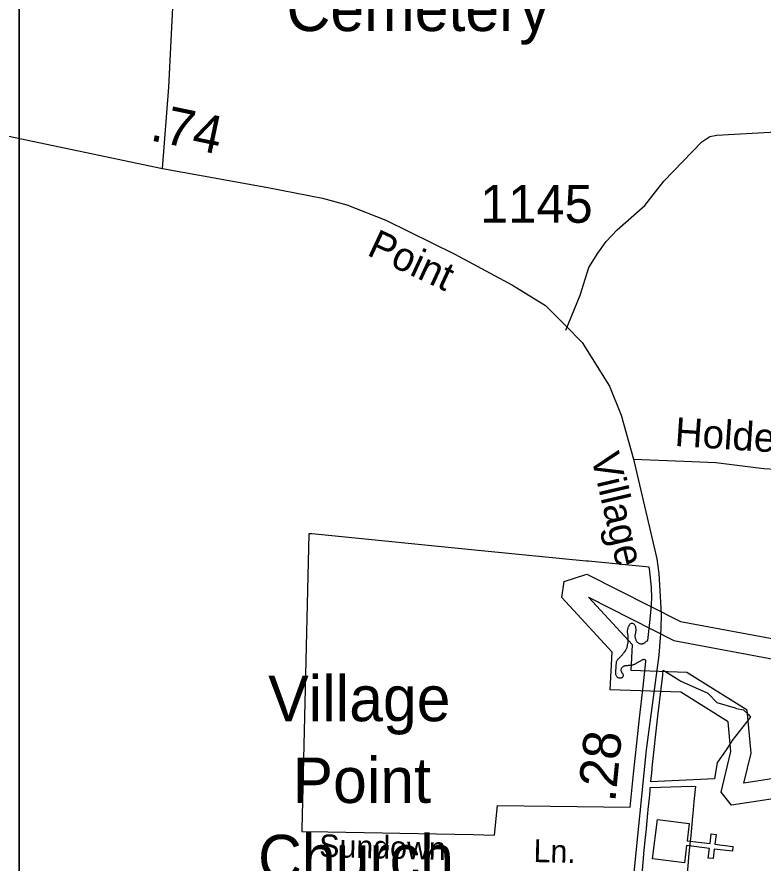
# Model space of a CAD drawing. Extents: x 2104537 to 2336408, y 34176 to 229611.
# Drawn here: x 2187492 to 2189957, y 65482 to 68278 of the extents above; entities that cross this region are included whole.
import ezdxf

# ---------------------------------------------------------------- set-up
doc = ezdxf.new("R2010")
doc.units = 0
for name, color, linetype in [('Exist Boundary Political City Limit New', 7, 'Continuous'), ('Exist Cultural Cemetery Label', 7, 'Continuous'), ('Exist Cultural Church CELL', 7, 'Continuous'), ('Exist Cultural Church Label', 7, 'Continuous'), ('Exist Hydrographic Buffer Line', 7, 'Continuous'), ('Exist Hydrographic River Shore', 7, 'Continuous'), ('Exist Road Non-System Type 51', 7, 'Continuous'), ('Exist Road Non-System Type 51 Label', 7, 'Continuous'), ('Exist Road Secondary Mileage Hundredths English Label', 7, 'Continuous'), ('Exist Road Secondary Type 51 Attributed', 7, 'Continuous'), ('Exist Road Secondary Type 51 Label', 7, 'Continuous'), ('Exist Road Secondary Type 51 Number Label', 7, 'Continuous'), ('Map Preparation Boundary City Limit Buffer Line', 7, 'Continuous'), ('Map Preparation Inset Cut Line', 7, 'Continuous')]:
    doc.layers.add(name, color=color, linetype=linetype)

msp = doc.modelspace()

# ---------------------------------------------------------------- linework, layer by layer
at = {"layer": 'Exist Boundary Political City Limit New'}
for points in [[(2189587, 66320.6), (2189589.5, 66356.8), (2189587.8, 66393.6), (2189583, 66444), (2189581.5, 66453.5), (2189580.5, 66459.3), (2189380, 66479.1), (2189372.5, 66479.8), (2189037.8, 66512.8), (2188466, 66569.2), (2188456.2, 66570.1), (2188433.2, 65593.1), (2188433, 65586.3), (2188518.8, 65584.7), (2188578.5, 65583.5), (2188639, 65582.4), (2188699.2, 65581.3), (2188757.2, 65580.2), (2188818.8, 65579), (2188877.8, 65577.9), (2188999, 65575.6), (2189070, 65574.2), (2189079, 65671.7), (2189517.5, 65666), (2189529, 65777), (2189540, 65878.1), (2189548.8, 65960.2), (2189560.2, 66064), (2189569.2, 66147.4), (2189569.8, 66151.6), (2189566, 66153.5), (2189564, 66154), (2189562.2, 66153.8), (2189560.2, 66153.4), (2189558.2, 66152.7), (2189556.2, 66152), (2189554.5, 66151.2), (2189552.8, 66150.2), (2189551, 66149.2), (2189549.2, 66148.1), (2189547.8, 66147.1), (2189546, 66146.1), (2189544.2, 66145), (2189542.5, 66144), (2189540.8, 66142.9), (2189539, 66141.9), (2189537.2, 66140.9), (2189535.5, 66140), (2189533.8, 66139.1), (2189532, 66138.3), (2189530, 66137.5), (2189528.2, 66136.7), (2189526.5, 66136), (2189524.5, 66135.4)], [(2189506.5, 66192), (2189507.2, 66193.9), (2189507.8, 66195.8), (2189508.2, 66197.7), (2189508.5, 66199.7), (2189508.8, 66201.7), (2189509.2, 66203.7), (2189509.8, 66205.6), (2189510.2, 66207.5), (2189511, 66209.4), (2189511, 66211.4), (2189511, 66213.4), (2189510.8, 66215.4), (2189510.5, 66218.5), (2189510.8, 66220.5), (2189511.2, 66222.5), (2189511.5, 66224.5), (2189511.5, 66226.5), (2189511.5, 66228.5), (2189511.5, 66230.4), (2189511.2, 66232.4), (2189510.8, 66234.4), (2189510.2, 66236.4), (2189510, 66238.3), (2189509.5, 66240.3), (2189509.2, 66242.3), (2189509.2, 66244.3), (2189509.2, 66246.3), (2189509.2, 66248.3), (2189509.2, 66250.3), (2189509.5, 66252.3), (2189509.8, 66254.3), (2189510, 66256.2), (2189510.8, 66258.1), (2189511.5, 66260), (2189512.2, 66261.8), (2189513, 66263.7), (2189514, 66265.5), (2189514.8, 66267.4), (2189515.8, 66269.2), (2189516.8, 66270.8), (2189518.2, 66272.1), (2189520, 66273.2), (2189522, 66274.1), (2189524, 66274.5), (2189525.8, 66274.2), (2189527.8, 66273.3), (2189529.2, 66272), (2189530.8, 66270.6), (2189532, 66269), (2189533, 66267.3), (2189534, 66265.4), (2189534.8, 66263.6), (2189535.2, 66261.7), (2189535.5, 66259.7), (2189535.8, 66257.7), (2189536, 66255.7), (2189536, 66253.7), (2189536.2, 66251.7), (2189536.2, 66249.7), (2189536, 66247.7), (2189535.8, 66245.7), (2189535.8, 66243.7), (2189535.2, 66241.7), (2189535, 66239.8), (2189534.2, 66237.8), (2189534, 66235.9), (2189533.5, 66233.9), (2189533.5, 66231.9), (2189533.5, 66229.9), (2189533.8, 66227.9), (2189534, 66225.9), (2189534.5, 66224), (2189535.2, 66222.1), (2189536, 66220.2), (2189536.8, 66218.4), (2189537.8, 66216.6), (2189538.8, 66214.9), (2189540, 66213.2), (2189541.2, 66211.7), (2189542.8, 66210.3), (2189544.2, 66209.3), (2189546.2, 66208.4), (2189548, 66207.7), (2189550, 66207.1), (2189552, 66206.6), (2189554, 66206.2), (2189556, 66206.1), (2189558, 66206.4), (2189559.8, 66206.9), (2189561.8, 66207.6), (2189563.5, 66208.6), (2189565.2, 66209.7), (2189566.8, 66211), (2189568.2, 66212.4), (2189569.8, 66213.6), (2189571.5, 66214.7), (2189576.5, 66217.4), (2189581.5, 66266.9), (2189587, 66320.6)], [(2189524.5, 66135.4), (2189522.5, 66134.9), (2189520.5, 66134.5), (2189518.5, 66134.2), (2189516.5, 66134), (2189514.5, 66134), (2189512.5, 66134), (2189510.5, 66134), (2189508.5, 66133.9), (2189506.5, 66133.8), (2189504.5, 66133.8), (2189502.5, 66133.6), (2189500.5, 66133.2), (2189498.8, 66132.7), (2189496.8, 66131.9), (2189495, 66131), (2189493.2, 66129.9), (2189491.8, 66128.6), (2189490.5, 66127.1), (2189489.2, 66125.4), (2189488.2, 66123.6), (2189487.2, 66121.7), (2189487, 66119.9), (2189487, 66118), (2189487.8, 66116.1), (2189488.5, 66114.2), (2189489.5, 66112.4), (2189490.5, 66110.6), (2189491.8, 66109), (2189493, 66107.3), (2189493.8, 66105.6), (2189494.2, 66103.6), (2189494.2, 66101.5), (2189494, 66099.5), (2189493.2, 66097.7), (2189492.2, 66095.9), (2189491, 66094.3), (2189489.5, 66093.2), (2189487.5, 66092.7), (2189485.2, 66092.6), (2189483.2, 66092.7), (2189481.2, 66092.9), (2189479.2, 66093.3), (2189477.5, 66094), (2189476, 66095.1), (2189474.5, 66096.6), (2189473.2, 66098.2), (2189472.2, 66100), (2189471.2, 66101.9), (2189470.5, 66103.8), (2189470, 66105.6), (2189470, 66107.6), (2189470, 66109.6), (2189470.2, 66111.7), (2189470.5, 66113.7), (2189470.5, 66115.7), (2189470.5, 66117.7), (2189470.8, 66119.7), (2189470.8, 66121.7), (2189471, 66123.7), (2189471, 66125.7), (2189471, 66127.7), (2189471.2, 66129.7), (2189471.2, 66131.7), (2189471.5, 66133.7), (2189471.5, 66135.7), (2189471.8, 66137.7), (2189472, 66139.7), (2189472.2, 66141.6), (2189472.5, 66143.6), (2189472.8, 66145.6), (2189473, 66147.6), (2189473.8, 66149.5), (2189474.5, 66151.4), (2189475.5, 66153), (2189476.8, 66154.5), (2189478.2, 66156), (2189479.8, 66157.4), (2189481, 66158.7), (2189482.5, 66160.1), (2189484, 66161.6), (2189485.5, 66163), (2189486.8, 66164.5), (2189488, 66166), (2189489.5, 66167.5), (2189490.8, 66169), (2189492, 66170.5), (2189493.2, 66172), (2189494.5, 66173.5), (2189495.8, 66175.1), (2189497, 66176.7), (2189498.2, 66178.3), (2189499.5, 66179.9), (2189500.5, 66181.5), (2189501.8, 66183.2), (2189502.8, 66184.9), (2189503.8, 66186.6), (2189504.8, 66188.4), (2189505.8, 66190.1), (2189506.5, 66192)], [(2189796.5, 65760.1), (2189586.2, 65750.3), (2189587.5, 65763.4), (2189588, 65768.5), (2189589, 65781.4), (2189589.2, 65782.4), (2189589.2, 65783.4), (2189589.2, 65784.4), (2189589.5, 65785.4), (2189589.5, 65786.4), (2189589.8, 65787.4), (2189589.8, 65788.4), (2189589.8, 65789), (2189590, 65790.1), (2189590, 65791.4), (2189590, 65792.4), (2189590.2, 65793.4), (2189590.2, 65794.4), (2189590.5, 65795.3), (2189590.5, 65796.3), (2189590.5, 65797.3), (2189608.5, 65966.6), (2189608.5, 65967.4), (2189625, 66102.3), (2189625.2, 66106), (2189627, 66119.2), (2189643.2, 66109.1), (2189661, 66098), (2189681.8, 66085.1), (2189685.2, 66083), (2189772, 66044.3), (2189774.5, 66043.1), (2189778.2, 66039.1), (2189804, 66012.2), (2189864.8, 65994.1), (2189869, 65992.7), (2189892.5, 65987.6), (2189893.2, 65986.9), (2189908, 65972.2), (2189911.8, 65968.5), (2189915.2, 65965.1), (2189913.5, 65963), (2189853.8, 65885.6), (2189853, 65884.6), (2189832.8, 65852.3), (2189806, 65815.2), (2189805.5, 65814.4), (2189796.5, 65760.1)], [(2189557, 65446.1), (2189561.8, 65496), (2189563.2, 65512.6), (2189566.5, 65546.2), (2189570.5, 65584.9), (2189571.5, 65596.1), (2189576.2, 65646.5), (2189577.2, 65657.4), (2189577.5, 65658.8), (2189581, 65696.6), (2189583.2, 65719.9), (2189583.2, 65720.8), (2189584.2, 65729.9), (2189584.2, 65731.4), (2189720.2, 65736.2), (2189733, 65735), (2189728.2, 65684.7), (2189724.5, 65645.1), (2189723.5, 65635.1), (2189718.8, 65585.4), (2189717.5, 65572.7), (2189714, 65535.3), (2189710.8, 65501.3), (2189710.8, 65500.2), (2189709.2, 65485.7), (2189704.5, 65435.6)]]:
    msp.add_lwpolyline(points, dxfattribs=at)
at = {"layer": 'Exist Cultural Church CELL'}
msp.add_lwpolyline([(2189713, 65612.1), (2189706, 65555.6), (2189781.6, 65546), (2189785.6, 65577.8), (2189801.4, 65575.8), (2189797.4, 65544), (2189857.1, 65536.5), (2189855.1, 65520.6), (2189795.4, 65528.1), (2189791.4, 65496.4), (2189775.5, 65498.4), (2189779.5, 65530.1), (2189704, 65539.7), (2189696.7, 65482.5), (2189591, 65495.9), (2189607.4, 65625.4)], close=True, dxfattribs=at)
at = {"layer": 'Exist Hydrographic Buffer Line'}
for points in [[(2189662.4, 66216.7), (2190025.8, 66149), (2190216, 65969.9), (2190365.6, 65971.5), (2190554.2, 66066), (2190758.2, 66107.2), (2190937.1, 66171.3), (2191044.4, 66151.1), (2191050.5, 66054.7), (2191019.5, 65933.3), (2191130.5, 65806.3), (2191649.9, 65837.9), (2191739.7, 66010.8), (2191753.9, 66423.1), (2191870.6, 66693.9), (2191804.3, 67417)], [(2189704.4, 66111.5), (2189520.9, 66117.7), (2189525.7, 66203), (2189380.4, 66359.9)], [(2189380.4, 66359.9), (2189662.4, 66216.7)], [(2190989.7, 63585.2), (2191114.3, 63707.3), (2191319.4, 63834.1), (2191604.9, 63949), (2191603, 64084.7), (2191508.3, 64270.6), (2191456.2, 64655.5), (2191305.3, 64951.5), (2191286, 65264.7), (2191188.9, 65407.1), (2191039.9, 65563.1), (2190793.9, 65645.6), (2190364.1, 65611.5), (2190190, 65689.2), (2190098.8, 65777.5), (2189893.2, 65745.3), (2189917, 65845), (2189904, 65986.7), (2189704.4, 66111.5)]]:
    msp.add_lwpolyline(points, dxfattribs=at)
at = {"layer": 'Exist Hydrographic River Shore'}
for points in [[(2189683.7, 66279.5), (2190056.7, 66210), (2190241.7, 66035.8), (2190349.7, 66037), (2190532.7, 66128.6), (2190740.6, 66170.6), (2190931.7, 66239.1), (2191106.6, 66206.1), (2191116.6, 66048.5), (2191091.6, 65950.5), (2191158.7, 65873.7), (2191608.8, 65901.2), (2191674.6, 66027.9), (2191688.7, 66437.7), (2191803.8, 66704.5), (2191739.6, 67404.6)], [(2189291.7, 66359.2), (2189299.7, 66411.6), (2189374.7, 66436.4), (2189683.7, 66279.5)], [(2189684.6, 66046.5), (2189451.6, 66054.4), (2189458.6, 66178.9), (2189291.7, 66359.2)], [(2190943.7, 63632), (2191073.6, 63759.2), (2191289.7, 63892.9), (2191538.6, 63993.1), (2191537.6, 64068.5), (2191444.7, 64250.8), (2191392.6, 64635.6), (2191240.7, 64933.9), (2191221.6, 65242.6), (2191137.8, 65365.6), (2191003.7, 65506), (2190785.7, 65579.1), (2190352.6, 65544.8), (2190152.7, 65634), (2190076.6, 65707.6), (2189852.7, 65672.6), (2189818.7, 65715.9), (2189850.6, 65849.8), (2189841.6, 65948.4), (2189684.6, 66046.5)]]:
    msp.add_lwpolyline(points, dxfattribs=at)
at = {"layer": 'Exist Road Non-System Type 51'}
for points in [[(2187973.5, 67777), (2187993.5, 68045.4), (2188016.4, 68485.5), (2188028, 68543.4), (2188038, 68568.1), (2188047.5, 68581.7), (2188063.5, 68597.8), (2188081.4, 68606.3), (2188101.5, 68611.5), (2188155.4, 68614.4), (2188309.1, 68608.5)], [(2189305.4, 67242.8), (2189352.3, 67358.7), (2189381.6, 67449.4), (2189411.1, 67497.3), (2189438.7, 67535.9), (2189474.2, 67574.2), (2189565.7, 67654.8), (2189628.9, 67734.9), (2189754.5, 67865.2), (2189780.4, 67882.6), (2189804.1, 67887.1), (2189940.1, 67895), (2190000.2, 67897.7)]]:
    msp.add_lwpolyline(points, dxfattribs=at)
at = {"layer": 'Exist Road Secondary Type 51 Attributed'}
for points in [[(2186197.2, 68413.4), (2186259.6, 68332.5), (2186324.3, 68265.4), (2186398.3, 68196.1), (2186458.3, 68147.5), (2186516.1, 68108.2), (2186666.3, 68050.4), (2186903.7, 68001.1), (2187973.5, 67777), (2188321.1, 67714.5), (2188501.3, 67679.2), (2188581.9, 67656.5), (2188710.4, 67606.1), (2188938.4, 67493.9), (2189128.5, 67391.6), (2189238.3, 67323.7), (2189303.8, 67258.2), (2189359.2, 67201.5), (2189449.2, 67057.6), (2189487.7, 66962.1), (2189529.2, 66816.3)], [(2189529.2, 66816.3), (2189606.1, 66487), (2189612.4, 66439), (2189619.7, 66305), (2189619.1, 66255.1), (2189612.8, 66169), (2189570, 65855.4), (2189527.3, 65428.1), (2189518.1, 65355.8)], [(2189529.2, 66816.3), (2189695.4, 66809.4), (2189800.3, 66805.1), (2189958.7, 66785), (2190074.7, 66778.5), (2190373.4, 66752.4), (2190743.7, 66727.2), (2190775.7, 66723.6), (2191086.3, 66697.6), (2191375.8, 66671.6), (2191503.1, 66656), (2191661.6, 66640.4)]]:
    msp.add_lwpolyline(points, dxfattribs=at)
at = {"layer": 'Map Preparation Boundary City Limit Buffer Line'}
for points in [[(2189587, 66320.6), (2189589.5, 66356.8), (2189587.8, 66393.6), (2189583, 66444), (2189581.5, 66453.5), (2189580.5, 66459.3), (2189380, 66479.1), (2189372.5, 66479.8), (2189037.8, 66512.8), (2188466, 66569.2), (2188456.2, 66570.1), (2188433.2, 65593.1), (2188433, 65586.3), (2188518.8, 65584.7), (2188578.5, 65583.5), (2188639, 65582.4), (2188699.2, 65581.3), (2188757.2, 65580.2), (2188818.8, 65579), (2188877.8, 65577.9), (2188999, 65575.6), (2189070, 65574.2), (2189079, 65671.7), (2189517.5, 65666), (2189529, 65777), (2189540, 65878.1), (2189548.8, 65960.2), (2189560.2, 66064), (2189569.2, 66147.4), (2189569.8, 66151.6), (2189566, 66153.5), (2189564, 66154), (2189562.2, 66153.8), (2189560.2, 66153.4), (2189558.2, 66152.7), (2189556.2, 66152), (2189554.5, 66151.2), (2189552.8, 66150.2), (2189551, 66149.2), (2189549.2, 66148.1), (2189547.8, 66147.1), (2189546, 66146.1), (2189544.2, 66145), (2189542.5, 66144), (2189540.8, 66142.9), (2189539, 66141.9), (2189537.2, 66140.9), (2189535.5, 66140), (2189533.8, 66139.1), (2189532, 66138.3), (2189530, 66137.5), (2189528.2, 66136.7), (2189526.5, 66136), (2189524.5, 66135.4)], [(2189506.5, 66192), (2189507.2, 66193.9), (2189507.8, 66195.8), (2189508.2, 66197.7), (2189508.5, 66199.7), (2189508.8, 66201.7), (2189509.2, 66203.7), (2189509.8, 66205.6), (2189510.2, 66207.5), (2189511, 66209.4), (2189511, 66211.4), (2189511, 66213.4), (2189510.8, 66215.4), (2189510.5, 66218.5), (2189510.8, 66220.5), (2189511.2, 66222.5), (2189511.5, 66224.5), (2189511.5, 66226.5), (2189511.5, 66228.5), (2189511.5, 66230.4), (2189511.2, 66232.4), (2189510.8, 66234.4), (2189510.2, 66236.4), (2189510, 66238.3), (2189509.5, 66240.3), (2189509.2, 66242.3), (2189509.2, 66244.3), (2189509.2, 66246.3), (2189509.2, 66248.3), (2189509.2, 66250.3), (2189509.5, 66252.3), (2189509.8, 66254.3), (2189510, 66256.2), (2189510.8, 66258.1), (2189511.5, 66260), (2189512.2, 66261.8), (2189513, 66263.7), (2189514, 66265.5), (2189514.8, 66267.4), (2189515.8, 66269.2), (2189516.8, 66270.8), (2189518.2, 66272.1), (2189520, 66273.2), (2189522, 66274.1), (2189524, 66274.5), (2189525.8, 66274.2), (2189527.8, 66273.3), (2189529.2, 66272), (2189530.8, 66270.6), (2189532, 66269), (2189533, 66267.3), (2189534, 66265.4), (2189534.8, 66263.6), (2189535.2, 66261.7), (2189535.5, 66259.7), (2189535.8, 66257.7), (2189536, 66255.7), (2189536, 66253.7), (2189536.2, 66251.7), (2189536.2, 66249.7), (2189536, 66247.7), (2189535.8, 66245.7), (2189535.8, 66243.7), (2189535.2, 66241.7), (2189535, 66239.8), (2189534.2, 66237.8), (2189534, 66235.9), (2189533.5, 66233.9), (2189533.5, 66231.9), (2189533.5, 66229.9), (2189533.8, 66227.9), (2189534, 66225.9), (2189534.5, 66224), (2189535.2, 66222.1), (2189536, 66220.2), (2189536.8, 66218.4), (2189537.8, 66216.6), (2189538.8, 66214.9), (2189540, 66213.2), (2189541.2, 66211.7), (2189542.8, 66210.3), (2189544.2, 66209.3), (2189546.2, 66208.4), (2189548, 66207.7), (2189550, 66207.1), (2189552, 66206.6), (2189554, 66206.2), (2189556, 66206.1), (2189558, 66206.4), (2189559.8, 66206.9), (2189561.8, 66207.6), (2189563.5, 66208.6), (2189565.2, 66209.7), (2189566.8, 66211), (2189568.2, 66212.4), (2189569.8, 66213.6), (2189571.5, 66214.7), (2189576.5, 66217.4), (2189581.5, 66266.9), (2189587, 66320.6)], [(2189524.5, 66135.4), (2189522.5, 66134.9), (2189520.5, 66134.5), (2189518.5, 66134.2), (2189516.5, 66134), (2189514.5, 66134), (2189512.5, 66134), (2189510.5, 66134), (2189508.5, 66133.9), (2189506.5, 66133.8), (2189504.5, 66133.8), (2189502.5, 66133.6), (2189500.5, 66133.2), (2189498.8, 66132.7), (2189496.8, 66131.9), (2189495, 66131), (2189493.2, 66129.9), (2189491.8, 66128.6), (2189490.5, 66127.1), (2189489.2, 66125.4), (2189488.2, 66123.6), (2189487.2, 66121.7), (2189487, 66119.9), (2189487, 66118), (2189487.8, 66116.1), (2189488.5, 66114.2), (2189489.5, 66112.4), (2189490.5, 66110.6), (2189491.8, 66109), (2189493, 66107.3), (2189493.8, 66105.6), (2189494.2, 66103.6), (2189494.2, 66101.5), (2189494, 66099.5), (2189493.2, 66097.7), (2189492.2, 66095.9), (2189491, 66094.3), (2189489.5, 66093.2), (2189487.5, 66092.7), (2189485.2, 66092.6), (2189483.2, 66092.7), (2189481.2, 66092.9), (2189479.2, 66093.3), (2189477.5, 66094), (2189476, 66095.1), (2189474.5, 66096.6), (2189473.2, 66098.2), (2189472.2, 66100), (2189471.2, 66101.9), (2189470.5, 66103.8), (2189470, 66105.6), (2189470, 66107.6), (2189470, 66109.6), (2189470.2, 66111.7), (2189470.5, 66113.7), (2189470.5, 66115.7), (2189470.5, 66117.7), (2189470.8, 66119.7), (2189470.8, 66121.7), (2189471, 66123.7), (2189471, 66125.7), (2189471, 66127.7), (2189471.2, 66129.7), (2189471.2, 66131.7), (2189471.5, 66133.7), (2189471.5, 66135.7), (2189471.8, 66137.7), (2189472, 66139.7), (2189472.2, 66141.6), (2189472.5, 66143.6), (2189472.8, 66145.6), (2189473, 66147.6), (2189473.8, 66149.5), (2189474.5, 66151.4), (2189475.5, 66153), (2189476.8, 66154.5), (2189478.2, 66156), (2189479.8, 66157.4), (2189481, 66158.7), (2189482.5, 66160.1), (2189484, 66161.6), (2189485.5, 66163), (2189486.8, 66164.5), (2189488, 66166), (2189489.5, 66167.5), (2189490.8, 66169), (2189492, 66170.5), (2189493.2, 66172), (2189494.5, 66173.5), (2189495.8, 66175.1), (2189497, 66176.7), (2189498.2, 66178.3), (2189499.5, 66179.9), (2189500.5, 66181.5), (2189501.8, 66183.2), (2189502.8, 66184.9), (2189503.8, 66186.6), (2189504.8, 66188.4), (2189505.8, 66190.1), (2189506.5, 66192)], [(2189796.5, 65760.1), (2189586.2, 65750.3), (2189587.5, 65763.4), (2189588, 65768.5), (2189589, 65781.4), (2189589.2, 65782.4), (2189589.2, 65783.4), (2189589.2, 65784.4), (2189589.5, 65785.4), (2189589.5, 65786.4), (2189589.8, 65787.4), (2189589.8, 65788.4), (2189589.8, 65789), (2189590, 65790.1), (2189590, 65791.4), (2189590, 65792.4), (2189590.2, 65793.4), (2189590.2, 65794.4), (2189590.5, 65795.3), (2189590.5, 65796.3), (2189590.5, 65797.3), (2189608.5, 65966.6), (2189608.5, 65967.4), (2189625, 66102.3), (2189625.2, 66106), (2189627, 66119.2), (2189643.2, 66109.1), (2189661, 66098), (2189681.8, 66085.1), (2189685.2, 66083), (2189772, 66044.3), (2189774.5, 66043.1), (2189778.2, 66039.1), (2189804, 66012.2), (2189864.8, 65994.1), (2189869, 65992.7), (2189892.5, 65987.6), (2189893.2, 65986.9), (2189908, 65972.2), (2189911.8, 65968.5), (2189915.2, 65965.1), (2189913.5, 65963), (2189853.8, 65885.6), (2189853, 65884.6), (2189832.8, 65852.3), (2189806, 65815.2), (2189805.5, 65814.4), (2189796.5, 65760.1)], [(2189557, 65446.1), (2189561.8, 65496), (2189563.2, 65512.6), (2189566.5, 65546.2), (2189570.5, 65584.9), (2189571.5, 65596.1), (2189576.2, 65646.5), (2189577.2, 65657.4), (2189577.5, 65658.8), (2189581, 65696.6), (2189583.2, 65719.9), (2189583.2, 65720.8), (2189584.2, 65729.9), (2189584.2, 65731.4), (2189720.2, 65736.2), (2189733, 65735), (2189728.2, 65684.7), (2189724.5, 65645.1), (2189723.5, 65635.1), (2189718.8, 65585.4), (2189717.5, 65572.7), (2189714, 65535.3), (2189710.8, 65501.3), (2189710.8, 65500.2), (2189709.2, 65485.7), (2189704.5, 65435.6)]]:
    msp.add_lwpolyline(points, dxfattribs=at)
at = {"layer": 'Map Preparation Inset Cut Line'}
for points in [[(2262949.2, 100213), (2187500, 100213), (2187500, 55964.5), (2244094.4, 55964.5), (2244094.4, 70118.4), (2262949.2, 70118.4)], [(2116896.5, 80445.9), (2116896.5, 37235.7), (2173491, 37235.7), (2173491, 50351.3), (2187500, 54765.8), (2187500, 55964.5), (2187500, 80446.6)]]:
    msp.add_lwpolyline(points, close=True, dxfattribs=at)

# ---------------------------------------------------------------- texts
at = {"layer": 'Exist Cultural Cemetery Label'}
msp.add_text('Cemetery', height=150, dxfattribs=at).set_placement((2188382.6, 68230.9))
at = {"layer": 'Exist Cultural Church Label'}
for s, p in [('Village', (2188322.2, 65950.4)), ('Point', (2188402.5, 65680.4)), ('Church', (2188288.6, 65424.9))]:
    msp.add_text(s, height=150, dxfattribs=at).set_placement(p)
at = {"layer": 'Exist Road Non-System Type 51 Label'}
for s, p in [('Sundown', (2188489.8, 65501.8)), ('Ln.', (2189197.8, 65485.1))]:
    msp.add_text(s, height=75, rotation=358.6486, dxfattribs=at).set_placement(p)
at = {"layer": 'Exist Road Secondary Mileage Hundredths English Label'}
for s, rotation, p in [('.74', 348.1718, (2187928.5, 67870.6)), ('.28', 84.2993, (2189468, 65680.6))]:
    msp.add_text(s, height=125, rotation=rotation, dxfattribs=at).set_placement(p)
at = {"layer": 'Exist Road Secondary Type 51 Label'}
for s, rotation, p in [('Point', 335.1084, (2188644.7, 67492.3)), ('Holden', 356.2317, (2189663.1, 66860.3)), ('Village', 283.1605, (2189387.5, 66826.4))]:
    msp.add_text(s, height=95, rotation=rotation, dxfattribs=at).set_placement(p)
at = {"layer": 'Exist Road Secondary Type 51 Number Label'}
msp.add_text('1145', height=125, dxfattribs=at).set_placement((2189022.1, 67597.4))

doc.saveas('drawing.dxf')
